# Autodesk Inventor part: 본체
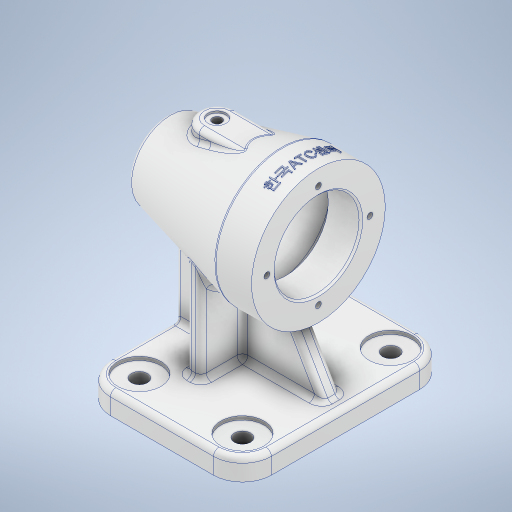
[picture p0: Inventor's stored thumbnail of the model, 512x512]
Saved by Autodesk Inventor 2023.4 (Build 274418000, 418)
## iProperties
Created: 2024-12
Part Number: 본체
Material: 알루미늄 6061
Document SubType Name: Modeling
Designer: EDU
Density: 2.7 g/cm^3
Appearance: 알루미늄 - 평지
Mass: 739.293 g
Surface Area: 673.866 cm^2
Volume: 273.812 cm^3
Author: EDU
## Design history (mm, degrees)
sketch "스케치1"
  geometry: L1 (0, 0)-(0, 21); L2 (0, 21)-(64, 37); L3 (0, 0)-(84, 0); L4 (-16.8, 0)-(100.8, 0) reference; L5 (64, 37)-(84, 37); L6 (84, 37)-(84, 0); 1 further point
  constraints: 10 end point, 2 horizontal, 1 coincident, 1 horizontal alignment, 1 perpendicular, 1 vertical
  dimensions: "d0" = 21 distance of L1.start L1.end; "d4" = 64 horizontal distance of L1.end L2.end; "d13" = 20 distance of L2.end L5.end; "d14" = 37 distance of L5.end L3.end
revolve "회전1" sketch "스케치1" stored, may be unused: angle "d6" = 90 deg
feature "쉘2" dims "d19" = 18, "d20" = 21, "d21" = 5
sketch "스케치5"
  geometry: C1 r 23.5 at (0, 0); 1 further point
  constraints: 1 centre point, 1 coincident
  dimensions: "d22" = 47 diameter of C1
extrude "돌출2" cut sketch "스케치5" distance "d23" = 18; taper "d24" = 0 deg
sketch "스케치6"
  geometry: C1 r 17.5 at (0, 0); 1 further point
  constraints: 1 centre point, 1 coincident
  dimensions: "d25" = 35 diameter of C1
extrude "돌출3" cut sketch "스케치6" distance "d26" = 10; taper "d27" = 0 deg
sketch "스케치7"
  geometry: C1 r 15.5 at (0, 0); 1 further point
  constraints: 1 centre point, 1 coincident
  dimensions: "d28" = 31 diameter of C1
extrude "돌출4" cut sketch "스케치7" distance "d29" = 3; taper "d30" = 0 deg
fillet "모깎기1" dims "d31" = 3
fillet "모깎기2" dims "d32" = 0.3
chamfer "모따기1" distance "d33" = 1; stored, may be unused: second distance "d34" = 2, angle "d35" = 45 deg
fillet "모깎기3" dims "d36" = 3
fillet "모깎기4" dims "d37" = 5
chamfer "모따기2" distance "d38" = 1; stored, may be unused: second distance "d39" = 2, angle "d40" = 45 deg
sketch "스케치8"
  geometry: C1 r 37 at (0, 0) reference; C2 r 24.5 at (0, 0) reference; A1 r 28.5 centre (0, 0) between (0, 28.5) and (0, -28.5); 3 further points
  constraints: 4 point on circle, 2 horizontal alignment, 2 vertical alignment, 1 centre point, 1 coincident
  dimensions: "d41" = 57 diameter of A1
hole "구멍1" sketch "스케치8" at (0, 28.5), (-28.5, 0), (28.5, 0), (0, -28.5) diameter "d42" = 3.242; stored, may be unused: countersink angle "d46" = 90 deg, drill point angle "d48" = 118 deg; dims "d43" = 8, "d44" = 4, "d45" = 2, "d47" = 10
node "작업 평면1"
sketch "스케치9"
  geometry: L1 (-10, 57)-(-99, 57); L2 (-99, 57)-(-99, -57); L3 (-99, -57)-(-10, -57); L4 (-10, -57)-(-10, 57); L5 (-84, 37)-(-84, -37) reference; 2 further points
  constraints: 8 end point, 2 parallel, 1 horizontal, 1 horizontal alignment, 1 midpoint, 1 perpendicular
  dimensions: "d50" = 114 distance between parallel lines of L1 L3; "d51" = 89 distance between parallel lines of L2 L4; "d52" = 15 distance between parallel lines of L2 L5
extrude "돌출5" join sketch "스케치9" distance "d53" = 12; taper "d54" = 0 deg
fillet "모깎기5" dims "d55" = 16
sketch "스케치10"
  geometry: L1 (83, 57)-(26, 57) reference; L2 (99, -41)-(99, 41) reference; L3 (26, -57)-(83, -57) reference; L4 (10, 41)-(10, -41) reference; A1 r 16 centre (26, 41) between (26, 57) and (10, 41) reference; A2 r 16 centre (83, 41) between (99, 41) and (83, 57) reference; A3 r 16 centre (83, -41) between (83, -57) and (99, -41) reference; A4 r 16 centre (26, -41) between (10, -41) and (26, -57) reference; 5 further points
  constraints: 4 coincident
hole "구멍2" sketch "스케치10" at (26, -41), (26, 41), (83, 41), (83, -41) diameter "d56" = 9; stored, may be unused: countersink angle "d60" = 90 deg, drill point angle "d62" = 118 deg; dims "d57" = 8, "d58" = 24, "d59" = 2, "d61" = 10
sketch "스케치11"
  geometry: L1 (83, 57)-(26, 57) reference; L2 (99, -41)-(99, 41) reference; L3 (26, -57)-(83, -57) reference; L4 (10, 41)-(10, -41) reference; L5 (10, 41)-(10, -41) reference; L6 (10, -5)-(39, -5); L7 (39, -5)-(39, -28); L8 (39, -28)-(47, -28); L9 (47, -28)-(47, 28); L10 (47, 28)-(39, 28); L11 (39, 28)-(39, 5); L12 (39, 5)-(10, 5); C1 r 4.5 at (83, 41) reference; C2 r 4.5 at (26, -41) reference; C3 r 4.5 at (26, 41) reference; C4 r 4.5 at (83, -41) reference; A1 r 16 centre (26, 41) between (26, 57) and (10, 41) reference; A2 r 16 centre (83, 41) between (99, 41) and (83, 57) reference; A3 r 16 centre (83, -41) between (83, -57) and (99, -41) reference; A4 r 16 centre (26, -41) between (10, -41) and (26, -57) reference; 5 further points
  constraints: 14 end point, 5 perpendicular, 4 point on line, 2 midpoint, 1 horizontal
  dimensions: "d63" = 10 distance between parallel lines of L6 L12; "d64" = 8 distance of L7.end L8.end; "d65" = 29 distance between parallel lines of L7 L4; "d66" = 56 distance between parallel lines of L10 L8; "d67" = 5 distance from line of L12 point (10, 0); "d68" = 28 distance from line of point (10, 0) L10
extrude "돌출6" join sketch "스케치11" stored distance "d69" = 12; taper "d70" = 0 deg
sketch "스케치12"
  geometry: L1 (47, -70)-(47, -16.987) reference; L2 (99, -70)-(99, -82) reference; L3 (83, -70)-(26, -70) reference; L4 (83, -70)-(99, -70) reference; L5 (99, -70)-(99, -82) reference; L6 (99, -82)-(83, -82) reference; L7 (83, -82)-(83, -70) reference; L8 (64, -37)-(84, -37) reference; L9 (0, -21)-(64, -37) reference; L10 (71, -70)-(95, -70) reference; L11 (92, -70)-(72.947, -37); 1 further point
  constraints: 2 end point, 2 point on line
  dimensions: "d71" = 7 distance of L2.start L11.start; "d72" = 60 deg angle of L4 L11
feature "리브1" sketch "스케치12" dims "d73" = 1, "d74" = 10, "d75" = 0, "d76" = 0, "d77" = 1, "d78" = 1
node "작업 평면2"
sketch "스케치13"
  geometry: L1 (-10, 37)-(-10, -37) reference; 3 further points
  constraints: 1 horizontal alignment, 1 midpoint, 1 other
  dimensions: "d79" = 9 distance from line of L1 point (-1, 0)
feature "엠보싱1" sketch "스케치13" dims "d0" = 21, "d80" = 0.5, "d81" = 0
node "작업 평면3"
sketch "스케치14"
  geometry: L1 (84, -37)-(84, 37) reference; L2 (28, 10)-(58, 10); L3 (28, -10)-(58, -10); L4 (58, 10)-(58, -10); A1 r 10 centre (28, 0) between (28, 10) and (28, -10); 2 further points
  constraints: 6 end point, 2 horizontal, 2 point on circle, 2 tangent, 1 centre point, 1 horizontal alignment, 1 midpoint, 1 vertical
  dimensions: "d83" = 20 diameter of A1; "d84" = 56 distance from line of L1 A1.centre; "d85" = 30 distance of L3.start L3.end
extrude "돌출7" join sketch "스케치14" stored distance "d86" = 10; taper "d87" = 0 deg
sketch "스케치15"
  geometry: L1 (84, -37)-(84, 37) reference; 2 further points
  constraints: 1 horizontal alignment
  dimensions: "d88" = 56 distance from line of L1 point (28, 0)
hole "구멍3" sketch "스케치15" at (28, 0) diameter "d89" = 5.1881; stored, may be unused: countersink angle "d93" = 90 deg, drill point angle "d95" = 0 deg; dims "d90" = 12, "d91" = 10, "d92" = 1, "d94" = 8
fillet "모깎기6" dims "d96" = 3
fillet "모깎기7" dims "d97" = 3
fillet "모깎기8" dims "d98" = 3
fillet "모깎기9" dims "d99" = 3
fillet "모깎기10" dims "d100" = 3
fillet "모깎기11" dims "d101" = 3
fillet "모깎기12" dims "d102" = 3
fillet "모깎기13" dims "d103" = 3
node "솔리드1"
node "투영된 루프1"
node "투영된 루프2"
node "투영된 루프3"
node "투영된 루프4"
feature "A9D066F2-1C7D-4E18-AEED-F7BC21143FA4" dims "d56" = 9, "d57" = 8, "d58" = 24, "d59" = 2, "d60" = 90 deg, "d61" = 10, "d62" = 118 deg
other parameters: "d49" = -82, "d82" = -115
